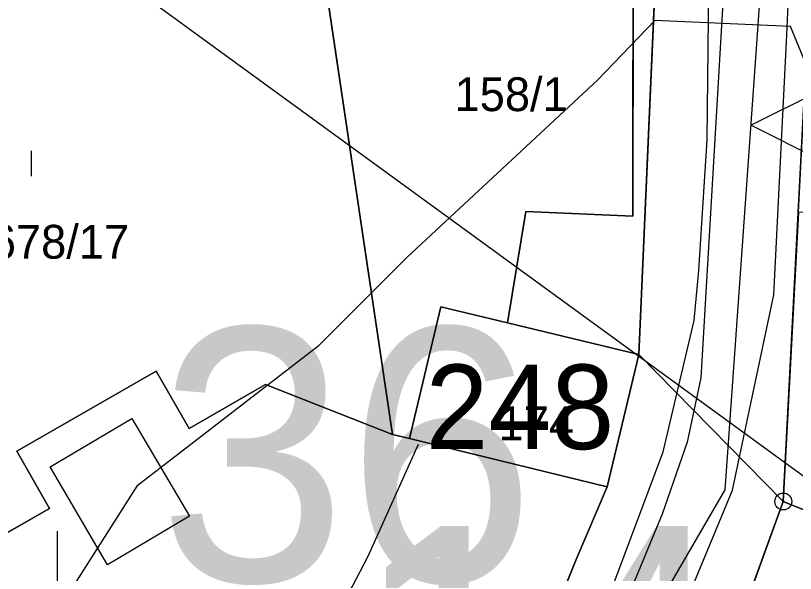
# Model space of a CAD drawing. Extents: x -706130 to -698555, y -971544 to -967260.
# Drawn here: x -704418.05 to -704371.94, y -970390.67 to -970357.67 of the extents above; entities that cross this region are included whole.
import ezdxf

# ---------------------------------------------------------------- set-up
doc = ezdxf.new("R2010")
doc.units = 0
for name, color, linetype in [('_Doplněk budov pro zastavěnost', 7, 'Continuous'), ('Archeologická naleziště S', 7, 'Continuous'), ('Architektonicky cenná stavba S', 7, 'Continuous'), ('BPEJ I-II trida ochrany S', 7, 'Continuous'), ('Docházková izochrona - VLAK N', 7, 'Continuous'), ('Hranice intravilán', 7, 'Continuous'), ('Implicitní', 7, 'Continuous'), ('Kanalizace_stoka bez rozlišení N', 7, 'Continuous'), ('KN_Budovy', 7, 'Continuous'), ('KN_Budovy_cisla_domovni', 7, 'Continuous'), ('KN_Hranice_parcel', 7, 'Continuous'), ('KN_Hranice_parcel_vnitrni_kresba', 7, 'Continuous'), ('KN_Parcelni cisla', 7, 'Continuous'), ('KN_Polygon parcely', 7, 'Continuous'), ('KN_POZEMKY_13_ZASTAVENA PLOCHA', 7, 'Continuous'), ('KN_POZEMKY_14_OSTATNI PLOCHA', 7, 'Continuous'), ('KN_POZEMKY_5_ZAHRADA', 7, 'Continuous'), ('KN_POZEMKY_7_TTP', 7, 'Continuous'), ('KN_VYUZITI_16_ostatni plocha_silnice', 7, 'Continuous'), ('KN_VYUZITI_17_ostatni plocha_ostatni komunikace', 7, 'Continuous'), ('KN_VYUZITI_20_ostatni plocha_sportoviste', 7, 'Continuous'), ('KN_Značky bodu BP', 7, 'Continuous'), ('KN_Značky budov', 7, 'Continuous'), ('KN_Značky kultur', 7, 'Continuous'), ('Komunikace III třídy osy S', 7, 'Continuous'), ('Kriticky bod pri privalovych srazkach popis S', 7, 'Continuous'), ('Kriticky bod pri privalovych srazkach S', 7, 'Continuous'), ('OP silnic S', 7, 'Continuous'), ('Plochy doprava silniční - silnice III třídy S', 7, 'Continuous'), ('Plochy smíšené obytné venkovské S', 7, 'Continuous'), ('Plynovody STL S', 7, 'Continuous'), ('Regulační bloky zastavěné S', 7, 'Continuous'), ('Stare ekologicke zateze popis S', 7, 'Continuous'), ('Trasy cykloturistické N', 7, 'Continuous'), ('Vodovodní řady - rozváděcí S', 7, 'Continuous'), ('VÝŠKOPIS_vrstevnice hlavní', 7, 'Continuous')]:
    doc.layers.add(name, color=color, linetype=linetype)

# ---------------------------------------------------------------- blocks, each defined once
blk = doc.blocks.new('UNNAMED')
at = {"layer": 'Implicitní'}
for p, q in [((0, -0.5), (0, 0.5)), ((-0.5, 0), (0.5, 0))]:
    blk.add_line(p, q, dxfattribs=at)

msp = doc.modelspace()

# ---------------------------------------------------------------- linework, layer by layer
at = {"layer": '_Doplněk budov pro zastavěnost'}
msp.add_lwpolyline([(-704416.01, -970384.37), (-704411.17, -970381.51), (-704407.77, -970387.29), (-704412.61, -970390.15)], close=True, dxfattribs=at)
at = {"layer": 'Archeologická naleziště S'}
msp.add_lwpolyline([(-704351.562, -970399.438), (-704434.562, -970338.938), (-704479.875, -969829.625), (-704673.438, -969453.375), (-704384.5, -968854), (-704158.5, -968821.188), (-704078.688, -969062.688), (-704202.938, -969793), (-704122.25, -969792.812), (-704213.312, -970265.25)], close=True, dxfattribs=at)
at = {"layer": 'Architektonicky cenná stavba S'}
msp.add_lwpolyline([(-704368.555, -970358.157), (-704370.555, -970362.157), (-704374.555, -970364.157), (-704370.555, -970366.157), (-704368.555, -970370.157), (-704366.555, -970366.157), (-704362.555, -970364.157), (-704366.555, -970362.157)], close=True, dxfattribs=at)
at = {"layer": 'BPEJ I-II trida ochrany S'}
for p, q in [((-704395.76, -970382.45), (-704400.12, -970353.14)), ((-704417.98, -970383.43), (-704409.73, -970378.7)), ((-704409.73, -970378.7), (-704407.78, -970382.09)), ((-704407.78, -970382.09), (-704403.26, -970379.5)), ((-704403.26, -970379.5), (-704395.76, -970382.45)), ((-704416.04, -970386.82), (-704417.98, -970383.43)), ((-704372.65, -970386.41), (-704375.12, -970393.19)), ((-704362.28, -970390.6), (-704372.65, -970386.41)), ((-704422.73, -970390.66), (-704416.04, -970386.82))]:
    msp.add_line(p, q, dxfattribs=at)
at = {"layer": 'Docházková izochrona - VLAK N'}
msp.add_circle((-704165.451, -969778.767), 800, dxfattribs=at)
at = {"layer": 'Hranice intravilán'}
for points in [[(-704412.74, -970420.26), (-704413.24, -970419.36), (-704421.1, -970404.49), (-704426.17, -970394.89), (-704421.76, -970392.36), (-704422.73, -970390.66), (-704416.04, -970386.82), (-704417.98, -970383.43), (-704409.73, -970378.7), (-704407.78, -970382.09), (-704403.26, -970379.5), (-704395.76, -970382.45), (-704394.76, -970382.69), (-704392.9, -970374.9), (-704388.96, -970375.85), (-704387.88, -970369.26), (-704381.54, -970369.54), (-704381.53, -970351.01)], [(-704362.28, -970390.6), (-704372.65, -970386.41), (-704375.12, -970393.19), (-704381.94, -970403.15), (-704386.46, -970409.76), (-704394.69, -970423.1)]]:
    msp.add_lwpolyline(points, dxfattribs=at)
at = {"layer": 'Kanalizace_stoka bez rozlišení N'}
msp.add_lwpolyline([(-704315.708, -970108.899), (-704316.113, -970109.917), (-704324.867, -970134.026), (-704326.632, -970179.784), (-704337.75, -970213.085), (-704365.425, -970272.107), (-704371.374, -970294.506), (-704373.709, -970351.804), (-704376.113, -970385.719), (-704398.194, -970423.758)], dxfattribs=at)
at = {"layer": 'KN_Budovy'}
msp.add_lwpolyline([(-704394.76, -970382.69), (-704383.07, -970385.55), (-704381.19, -970377.72), (-704388.96, -970375.85), (-704392.9, -970374.9)], close=True, dxfattribs=at)
at = {"layer": 'KN_Hranice_parcel'}
for p, q in [((-704400.12, -970353.14), (-704395.76, -970382.45)), ((-704371.76, -970369.3), (-704372.65, -970386.41)), ((-704381.19, -970377.72), (-704388.96, -970375.85)), ((-704381.19, -970377.72), (-704372.65, -970386.41)), ((-704372.65, -970386.41), (-704362.28, -970390.6))]:
    msp.add_line(p, q, dxfattribs=at)
for points in [[(-704381.19, -970377.72), (-704380.01, -970350.84), (-704377.78, -970300.1), (-704377.45, -970297.32)], [(-704388.96, -970375.85), (-704387.88, -970369.26), (-704381.54, -970369.54), (-704381.53, -970351.01)], [(-704388.96, -970375.85), (-704392.9, -970374.9), (-704394.76, -970382.69), (-704395.76, -970382.45)], [(-704387.19, -970395.46), (-704384.89, -970389.85), (-704383.07, -970385.55), (-704381.19, -970377.72)], [(-704395.76, -970382.45), (-704403.26, -970379.5), (-704407.78, -970382.09), (-704409.73, -970378.7), (-704417.98, -970383.43), (-704416.04, -970386.82), (-704422.73, -970390.66), (-704421.76, -970392.36), (-704426.17, -970394.89)], [(-704372.65, -970386.41), (-704375.12, -970393.19), (-704381.94, -970403.15)]]:
    msp.add_lwpolyline(points, dxfattribs=at)
at = {"layer": 'KN_Hranice_parcel_vnitrni_kresba'}
msp.add_line((-704383.07, -970385.55), (-704394.76, -970382.69), dxfattribs=at)
at = {"layer": 'KN_Polygon parcely'}
for points in [[(-704375.62, -970282.06), (-704376.41, -970288.62), (-704377.45, -970297.32), (-704377.78, -970300.1), (-704380.01, -970350.84), (-704381.19, -970377.72), (-704372.65, -970386.41), (-704371.76, -970369.3), (-704370.91, -970352.79), (-704370.59, -970346.53), (-704370.18, -970335.17), (-704369.52, -970316.88), (-704369.23, -970310.61), (-704368.75, -970300.09), (-704366.65, -970284.79), (-704361.08, -970269.38)], [(-704394.69, -970423.1), (-704386.46, -970409.76), (-704381.94, -970403.15), (-704375.12, -970393.19), (-704372.65, -970386.41), (-704381.19, -970377.72), (-704383.07, -970385.55), (-704384.89, -970389.85), (-704387.19, -970395.46), (-704392.51, -970404.97), (-704410.54, -970434.28)]]:
    msp.add_lwpolyline(points, dxfattribs=at)
for points in [[(-704426.17, -970394.89), (-704421.76, -970392.36), (-704422.73, -970390.66), (-704416.04, -970386.82), (-704417.98, -970383.43), (-704409.73, -970378.7), (-704407.78, -970382.09), (-704403.26, -970379.5), (-704395.76, -970382.45), (-704400.12, -970353.14), (-704404.67, -970353.65), (-704436.16, -970357.37), (-704435.41, -970332.61), (-704434.49, -970307.92), (-704433.21, -970284.34), (-704437.36, -970284.18), (-704440.6, -970365.1), (-704426.93, -970393.32)], [(-704381.19, -970377.72), (-704380.01, -970350.84), (-704377.78, -970300.1), (-704377.45, -970297.32), (-704381.06, -970296.88), (-704381.15, -970298.64), (-704382.31, -970309.38), (-704382.57, -970312.21), (-704382.15, -970324.47), (-704382.07, -970327.37), (-704381.84, -970335.31), (-704381.53, -970351.01), (-704381.54, -970369.54), (-704387.88, -970369.26), (-704388.96, -970375.85)], [(-704387.88, -970369.26), (-704381.54, -970369.54), (-704381.53, -970351.01), (-704391.93, -970352.2), (-704395.26, -970352.58), (-704400.12, -970353.14), (-704395.76, -970382.45), (-704394.76, -970382.69), (-704392.9, -970374.9), (-704388.96, -970375.85)], [(-704362.92, -970369.92), (-704365.94, -970369.84), (-704370.32, -970369.37), (-704371.76, -970369.3), (-704372.65, -970386.41), (-704362.28, -970390.6), (-704361.36, -970382.09), (-704360.53, -970374.44), (-704358.27, -970374.69)], [(-704381.19, -970377.72), (-704388.96, -970375.85), (-704392.9, -970374.9), (-704394.76, -970382.69), (-704395.76, -970382.45), (-704403.26, -970379.5), (-704407.78, -970382.09), (-704409.73, -970378.7), (-704417.98, -970383.43), (-704416.04, -970386.82), (-704422.73, -970390.66), (-704421.76, -970392.36), (-704426.17, -970394.89), (-704421.1, -970404.49), (-704413.24, -970419.36), (-704403.45, -970413.95), (-704396.57, -970408.3), (-704394.66, -970405.16), (-704388.72, -970394.62), (-704387.19, -970395.46), (-704384.89, -970389.85), (-704383.07, -970385.55)], [(-704375.12, -970393.19), (-704381.94, -970403.15), (-704349.12, -970414.28), (-704347.89, -970396.42), (-704362.28, -970390.6), (-704372.65, -970386.41)]]:
    msp.add_lwpolyline(points, close=True, dxfattribs=at)
at = {"layer": 'KN_POZEMKY_13_ZASTAVENA PLOCHA'}
for p, q in [((-704372.65, -970386.41), (-704371.76, -970369.3)), ((-704394.76, -970382.69), (-704392.9, -970374.9)), ((-704392.9, -970374.9), (-704388.96, -970375.85)), ((-704388.96, -970375.85), (-704381.19, -970377.72)), ((-704381.19, -970377.72), (-704383.07, -970385.55)), ((-704417.98, -970383.43), (-704409.73, -970378.7)), ((-704409.73, -970378.7), (-704407.78, -970382.09)), ((-704407.78, -970382.09), (-704403.26, -970379.5)), ((-704403.26, -970379.5), (-704395.76, -970382.45)), ((-704395.76, -970382.45), (-704394.76, -970382.69)), ((-704416.04, -970386.82), (-704417.98, -970383.43)), ((-704383.07, -970385.55), (-704384.89, -970389.85)), ((-704362.28, -970390.6), (-704372.65, -970386.41)), ((-704422.73, -970390.66), (-704416.04, -970386.82)), ((-704384.89, -970389.85), (-704387.19, -970395.46))]:
    msp.add_line(p, q, dxfattribs=at)
at = {"layer": 'KN_POZEMKY_14_OSTATNI PLOCHA'}
for p, q in [((-704381.53, -970351.01), (-704381.54, -970369.54)), ((-704381.54, -970369.54), (-704381.53, -970351.01)), ((-704381.19, -970377.72), (-704380.01, -970350.84)), ((-704380.01, -970350.84), (-704381.19, -970377.72)), ((-704395.76, -970382.45), (-704400.12, -970353.14)), ((-704387.88, -970369.26), (-704388.96, -970375.85)), ((-704388.96, -970375.85), (-704387.88, -970369.26)), ((-704381.54, -970369.54), (-704387.88, -970369.26)), ((-704387.88, -970369.26), (-704381.54, -970369.54)), ((-704371.76, -970369.3), (-704372.65, -970386.41)), ((-704392.9, -970374.9), (-704394.76, -970382.69)), ((-704388.96, -970375.85), (-704392.9, -970374.9)), ((-704381.19, -970377.72), (-704388.96, -970375.85)), ((-704383.07, -970385.55), (-704381.19, -970377.72)), ((-704381.19, -970377.72), (-704372.65, -970386.41)), ((-704372.65, -970386.41), (-704381.19, -970377.72)), ((-704394.76, -970382.69), (-704395.76, -970382.45)), ((-704384.89, -970389.85), (-704383.07, -970385.55)), ((-704372.65, -970386.41), (-704375.12, -970393.19)), ((-704387.19, -970395.46), (-704384.89, -970389.85))]:
    msp.add_line(p, q, dxfattribs=at)
at = {"layer": 'KN_POZEMKY_5_ZAHRADA'}
for p, q in [((-704375.12, -970393.19), (-704372.65, -970386.41)), ((-704372.65, -970386.41), (-704362.28, -970390.6))]:
    msp.add_line(p, q, dxfattribs=at)
at = {"layer": 'KN_POZEMKY_7_TTP'}
for p, q in [((-704400.12, -970353.14), (-704395.76, -970382.45)), ((-704409.73, -970378.7), (-704417.98, -970383.43)), ((-704407.78, -970382.09), (-704409.73, -970378.7)), ((-704403.26, -970379.5), (-704407.78, -970382.09)), ((-704395.76, -970382.45), (-704403.26, -970379.5)), ((-704417.98, -970383.43), (-704416.04, -970386.82)), ((-704416.04, -970386.82), (-704422.73, -970390.66))]:
    msp.add_line(p, q, dxfattribs=at)
at = {"layer": 'KN_VYUZITI_16_ostatni plocha_silnice'}
for p, q in [((-704381.19, -970377.72), (-704380.01, -970350.84)), ((-704371.76, -970369.3), (-704372.65, -970386.41)), ((-704383.07, -970385.55), (-704381.19, -970377.72)), ((-704381.19, -970377.72), (-704372.65, -970386.41)), ((-704372.65, -970386.41), (-704381.19, -970377.72)), ((-704384.89, -970389.85), (-704383.07, -970385.55)), ((-704372.65, -970386.41), (-704375.12, -970393.19)), ((-704387.19, -970395.46), (-704384.89, -970389.85))]:
    msp.add_line(p, q, dxfattribs=at)
at = {"layer": 'KN_VYUZITI_17_ostatni plocha_ostatni komunikace'}
for p, q in [((-704381.54, -970369.54), (-704381.53, -970351.01)), ((-704380.01, -970350.84), (-704381.19, -970377.72)), ((-704388.96, -970375.85), (-704387.88, -970369.26)), ((-704387.88, -970369.26), (-704381.54, -970369.54)), ((-704381.19, -970377.72), (-704388.96, -970375.85))]:
    msp.add_line(p, q, dxfattribs=at)
at = {"layer": 'KN_VYUZITI_20_ostatni plocha_sportoviste'}
for p, q in [((-704381.53, -970351.01), (-704381.54, -970369.54)), ((-704395.76, -970382.45), (-704400.12, -970353.14)), ((-704387.88, -970369.26), (-704388.96, -970375.85)), ((-704381.54, -970369.54), (-704387.88, -970369.26)), ((-704392.9, -970374.9), (-704394.76, -970382.69)), ((-704388.96, -970375.85), (-704392.9, -970374.9)), ((-704394.76, -970382.69), (-704395.76, -970382.45))]:
    msp.add_line(p, q, dxfattribs=at)
at = {"layer": 'KN_Značky bodu BP'}
for radius in [0.5, 0.0303]:
    msp.add_circle((-704372.65, -970386.41), radius, dxfattribs=at)
at = {"layer": 'KN_Značky budov'}
msp.add_circle((-704387.717, -970378.579), 0.175, dxfattribs=at)
at = {"layer": 'KN_Značky kultur'}
msp.add_line((-704417.11, -970367.17), (-704417.11, -970365.67), dxfattribs=at)
at = {"layer": 'Komunikace III třídy osy S'}
msp.add_lwpolyline([(-704330.93, -970188.51), (-704335.437, -970204.681), (-704336.48, -970208.22), (-704338.18, -970213.14), (-704340.791, -970218.395), (-704362.238, -970261.156), (-704368.668, -970276.027), (-704371.631, -970286.925), (-704374.154, -970304.881), (-704375.815, -970349.829), (-704377.52, -970379.09), (-704378.33, -970382.9), (-704379.81, -970387.16), (-704381.8, -970391.97), (-704383.72, -970396.25), (-704386.32, -970401.18), (-704392.36, -970410.73), (-704399.98, -970422.96)], dxfattribs=at)
at = {"layer": 'OP silnic S'}
msp.add_lwpolyline([(-704394.238, -970383.049), (-704397.21, -970389.675), (-704399.313, -970393.661), (-704405.064, -970402.755), (-704412.691, -970414.996), (-704430.611, -970443.433)], dxfattribs=at)
at = {"layer": 'Plochy doprava silniční - silnice III třídy S'}
for p, q in [((-704380.01, -970350.84), (-704381.19, -970377.72)), ((-704372.65, -970386.41), (-704371.76, -970369.3)), ((-704381.19, -970377.72), (-704383.07, -970385.55)), ((-704383.07, -970385.55), (-704384.89, -970389.85)), ((-704375.12, -970393.19), (-704372.65, -970386.41)), ((-704384.89, -970389.85), (-704387.19, -970395.46))]:
    msp.add_line(p, q, dxfattribs=at)
at = {"layer": 'Plochy smíšené obytné venkovské S'}
for p, q in [((-704381.19, -970377.72), (-704380.01, -970350.84)), ((-704371.76, -970369.3), (-704372.65, -970386.41)), ((-704383.07, -970385.55), (-704381.19, -970377.72)), ((-704384.89, -970389.85), (-704383.07, -970385.55)), ((-704372.65, -970386.41), (-704375.12, -970393.19)), ((-704387.19, -970395.46), (-704384.89, -970389.85))]:
    msp.add_line(p, q, dxfattribs=at)
at = {"layer": 'Plynovody STL S'}
msp.add_lwpolyline([(-704398.39, -970427.39), (-704384.69, -970404.86), (-704379.67, -970395.45), (-704375.66, -970385.74), (-704373.212, -970374.188), (-704372.471, -970359.213), (-704372.11, -970351.39), (-704379.05, -970351.42), (-704379.051, -970351.17), (-704378.94, -970349.71), (-704378.15, -970320.65), (-704377.62, -970309.79), (-704376.7, -970299.55), (-704375.786, -970291.541), (-704375.67, -970290.6), (-704375.535, -970290.001), (-704372.96, -970278.67)], dxfattribs=at)
at = {"layer": 'Regulační bloky zastavěné S'}
for p, q in [((-704381.19, -970377.72), (-704380.01, -970350.84)), ((-704380.01, -970350.84), (-704381.19, -970377.72)), ((-704371.76, -970369.3), (-704372.65, -970386.41)), ((-704372.65, -970386.41), (-704371.76, -970369.3)), ((-704383.07, -970385.55), (-704381.19, -970377.72)), ((-704381.19, -970377.72), (-704383.07, -970385.55)), ((-704384.89, -970389.85), (-704383.07, -970385.55)), ((-704383.07, -970385.55), (-704384.89, -970389.85)), ((-704372.65, -970386.41), (-704375.12, -970393.19)), ((-704375.12, -970393.19), (-704372.65, -970386.41)), ((-704387.19, -970395.46), (-704384.89, -970389.85)), ((-704384.89, -970389.85), (-704387.19, -970395.46))]:
    msp.add_line(p, q, dxfattribs=at)
at = {"layer": 'Trasy cykloturistické N'}
msp.add_lwpolyline([(-704397.28, -970427.29), (-704386.46, -970409.76), (-704381.94, -970403.15), (-704375.12, -970393.19), (-704372.65, -970386.41), (-704370.59, -970346.53), (-704369.52, -970316.88), (-704368.75, -970300.09), (-704366.65, -970284.79), (-704361.08, -970269.38), (-704350.46, -970248.43), (-704337.45, -970223.6), (-704330.57, -970211.6), (-704328.2, -970197.68), (-704324.27, -970184.8)], dxfattribs=at)
at = {"layer": 'Vodovodní řady - rozváděcí S'}
msp.add_lwpolyline([(-704404.59, -970428.41), (-704404.4, -970428.06), (-704389.04, -970403.19), (-704382.84, -970391.74), (-704379.76, -970383.48), (-704377.93, -970375.71), (-704377.64, -970372.75), (-704377.15, -970365.02), (-704376.91, -970343.31), (-704376.47, -970324.43), (-704376.46, -970319.47), (-704375.71, -970303.28), (-704375.47, -970302.37), (-704374.67, -970295.69), (-704373.36, -970287.93), (-704370.399, -970278.264)], dxfattribs=at)
at = {"layer": 'VÝŠKOPIS_vrstevnice hlavní'}
msp.add_lwpolyline([(-704367.365, -970370.105), (-704372.222, -970358.306), (-704380.242, -970357.968), (-704383.646, -970361.488), (-704394.9, -970371.959), (-704400.179, -970377.239), (-704410.879, -970385.514), (-704414.874, -970391.791), (-704425.289, -970411.194), (-704430.568, -970418.185), (-704435.561, -970422.608)], dxfattribs=at)

# ---------------------------------------------------------------- block references
at = {"layer": 'Kriticky bod pri privalovych srazkach S', "xscale": 11.925263, "yscale": 11.925263}
msp.add_blockref('UNNAMED', (-704415.574, -970394.128), dxfattribs=at)

# ---------------------------------------------------------------- texts
at = {"layer": 'KN_Budovy_cisla_domovni'}
msp.add_text('248', height=5, dxfattribs=at).set_placement((-704393.807, -970383.314))
at = {"layer": 'KN_Parcelni cisla'}
for s, p in [('158/1', (-704392.09, -970363.32)), ('1678/17', (-704421, -970372.049)), ('174', (-704389.49, -970382.789))]:
    msp.add_text(s, height=2, dxfattribs=at).set_placement(p)
at = {"layer": 'Kriticky bod pri privalovych srazkach popis S'}
msp.add_text('36', height=15, dxfattribs=at).set_placement((-704409.611, -970391.146))
at = {"layer": 'Stare ekologicke zateze popis S'}
msp.add_text('14471002 J okraj obce', height=15, dxfattribs=at).set_placement((-704398.08, -970402.857))

doc.saveas('drawing.dxf')
